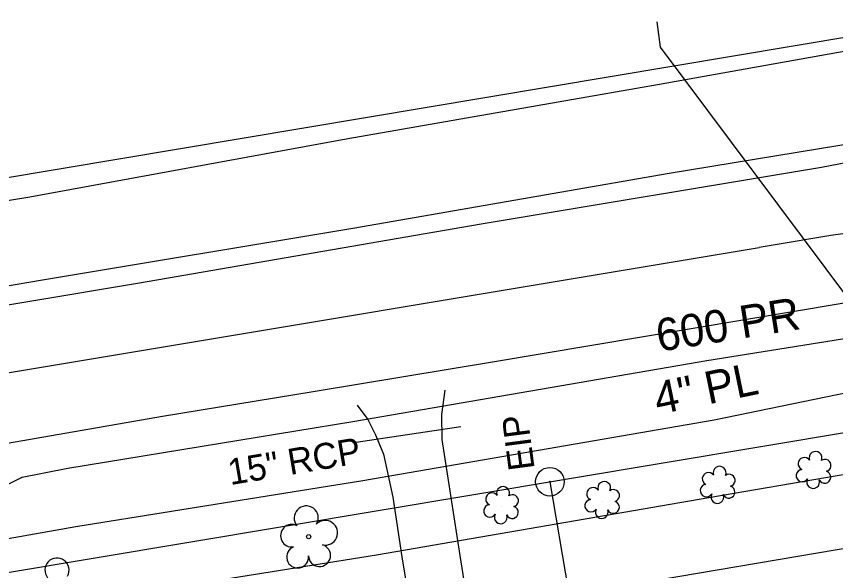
# Model space of a CAD drawing. Extents: x 2364404 to 2371833, y 798876 to 809754.
# Drawn here: x 2368108.5 to 2368234.7, y 807874.9 to 807960.2 of the extents above; entities that cross this region are included whole.
import ezdxf

# ---------------------------------------------------------------- set-up
doc = ezdxf.new("R2010")
doc.units = 0
for name, color, linetype in [('Exist Property Iron Pin CELL', 7, 'Continuous'), ('Exist Property Iron Pin Text', 7, 'Continuous'), ('Exist Property Line', 7, 'Continuous'), ('Exist Right of Way Line', 7, 'Continuous'), ('Exist Roads EOP', 7, 'Continuous'), ('Exist Roads EOP Other', 7, 'Continuous'), ('Exist Structure Minor Pipes RCP 15 Inch', 7, 'Continuous'), ('Exist Structure Minor Pipes RCP 15 Inch Text', 7, 'Continuous'), ('Exist Utilities Gas UG Line SUE LOS B', 7, 'Continuous'), ('Exist Utilities Gas UG Line SUE LOS B Text', 7, 'Continuous'), ('Exist Utilities Other Unknown UG SUE LOS B', 7, 'Continuous'), ('Exist Utilities Sanitary Sewer Manhole Leader', 7, 'Continuous'), ('Exist Utilities Sanitary Sewer UG Line', 7, 'Continuous'), ('Exist Utilities Telephone UG Cable SUE LOS C', 7, 'Continuous'), ('Exist Utilities Telephone UG Cable SUE LOS C Text', 7, 'Continuous'), ('Exist Utilities Water UG Line SUE LOS B', 7, 'Continuous'), ('Exist Vegetation Shrub CELL', 7, 'Continuous'), ('Exist Vegetation Tree CELL', 7, 'Continuous'), ('Prop Horizontal Alignment', 7, 'Continuous')]:
    doc.layers.add(name, color=color, linetype=linetype)

msp = doc.modelspace()

# ---------------------------------------------------------------- linework, layer by layer
at = {"layer": 'Exist Property Iron Pin CELL'}
for radius in [2.2, 0.0707]:
    msp.add_circle((2368190.72, 807888.59), radius, dxfattribs=at)
at = {"layer": 'Exist Property Line'}
msp.add_line((2368190.72, 807888.59), (2368217.51, 807729.25), dxfattribs=at)
at = {"layer": 'Exist Right of Way Line'}
for p, q in [((2367783.4, 807881.3), (2368349.02, 807975.89)), ((2367793.29, 807822.12), (2368269.46, 807901.75))]:
    msp.add_line(p, q, dxfattribs=at)
at = {"layer": 'Exist Roads EOP'}
for points in [[(2368327.15, 807956.52), (2368274.91, 807945.11), (2368232.58, 807936.97), (2368180.11, 807928.25), (2368127.18, 807919.09), (2368078.92, 807911.06), (2368034.07, 807903.44), (2367984.59, 807895.5), (2367945.39, 807888.89), (2367894.54, 807880.53), (2367863.53, 807875.21)], [(2368330.68, 807929.12), (2368282.89, 807923.49), (2368257.36, 807919.77), (2368235.72, 807916.02), (2368181.87, 807907), (2368154.26, 807902.43), (2368131.05, 807898.62), (2368082.95, 807890.29), (2368062.8, 807887.28), (2368038.08, 807883.12), (2367986.91, 807874.75), (2367949.87, 807868.19), (2367928.8, 807864.78), (2367897.29, 807860.14), (2367866.78, 807854.91)]]:
    msp.add_lwpolyline(points, dxfattribs=at)
at = {"layer": 'Exist Roads EOP Other'}
for points in [[(2368177.69, 807872.38), (2368176.91, 807877.23), (2368174.13, 807895.07), (2368174.09, 807898.92), (2368174.61, 807902.68)], [(2368161.02, 807900.36), (2368162.68, 807898.15), (2368163.84, 807895.79), (2368165.08, 807892.84), (2368166.53, 807886.21), (2368167.93, 807877.03), (2368172.78, 807847.56), (2368173.28, 807844.37), (2368175.23, 807832.75), (2368176.39, 807825.31)]]:
    msp.add_lwpolyline(points, dxfattribs=at)
at = {"layer": 'Exist Structure Minor Pipes RCP 15 Inch'}
msp.add_line((2368160.87, 807894.67), (2368176.98, 807897.08), dxfattribs=at)
at = {"layer": 'Exist Utilities Gas UG Line SUE LOS B'}
msp.add_lwpolyline([(2367870.54, 807838.09), (2367919.9, 807848.3), (2367968.48, 807855.53), (2368019.02, 807864.91), (2368064.26, 807872.88), (2368067.9, 807873.62), (2368094.51, 807877.58), (2368117.72, 807881.71), (2368161.92, 807888.8), (2368216.03, 807898.12), (2368260.65, 807907.32), (2368261.62, 807907.37), (2368282.45, 807912.12), (2368324.46, 807917.31), (2368347.86, 807919.04), (2368361.63, 807920.36), (2368385.5, 807921.08), (2368411.16, 807923.46), (2368412.54, 807923.08), (2368413.42, 807922.79)], dxfattribs=at)
at = {"layer": 'Exist Utilities Other Unknown UG SUE LOS B'}
msp.add_lwpolyline([(2367865.57, 807879.8), (2367916.68, 807886.76), (2367964.49, 807894.84), (2368013.92, 807902.8), (2368064.67, 807911.52), (2368112.58, 807919.65), (2368160.35, 807927.6), (2368209.07, 807936.09), (2368258.24, 807944.17), (2368305.66, 807951.87), (2368307.29, 807951.95), (2368330.7, 807955.87), (2368334.34, 807955.66), (2368336.05, 807954.46), (2368339.82, 807934.59), (2368342.66, 807932.92)], dxfattribs=at)
at = {"layer": 'Exist Utilities Sanitary Sewer Manhole Leader'}
msp.add_lwpolyline([(2368262.28, 807882.59), (2368207.76, 807955.48), (2368207.26, 807959.36)], dxfattribs=at)
at = {"layer": 'Exist Utilities Sanitary Sewer UG Line'}
msp.add_line((2368261.35, 807882.59), (2368017.75, 807841.36), dxfattribs=at)
at = {"layer": 'Exist Utilities Telephone UG Cable SUE LOS C'}
msp.add_lwpolyline([(2368104.4, 807876.72), (2368103.94, 807878.32), (2368103.75, 807883), (2368105.99, 807887.59), (2368109.41, 807889.3), (2368116.46, 807890.7), (2368160.35, 807897.88), (2368214.89, 807907.23), (2368259.58, 807914.4), (2368278.5, 807917.6), (2368324.44, 807924.48), (2368339.22, 807921.35), (2368348.06, 807912.11)], dxfattribs=at)
at = {"layer": 'Exist Utilities Water UG Line SUE LOS B'}
for points in [[(2368061.12, 807924.34), (2368110.63, 807932.44), (2368159.36, 807941.39), (2368207.29, 807949.76), (2368255.89, 807958.43), (2368303.66, 807970.11), (2368352.63, 807978.95), (2368406.52, 807986), (2368411.88, 807987.17), (2368430.69, 807989.56), (2368458.99, 807991.26), (2368504.63, 807993.63), (2368554.73, 807997.73), (2368558.03, 807998.11), (2368591.16, 808002.04), (2368605.81, 808004.45), (2368655.67, 808012.45), (2368680.36, 808015.78), (2368688.31, 808016.66)], [(2367871.12, 807828.45), (2367892.35, 807831.6), (2367921.84, 807837.39), (2367970.56, 807845.14), (2367984.76, 807847.38), (2368021.81, 807852.73), (2368062.83, 807858.73), (2368070.48, 807860.37), (2368122.26, 807870.75), (2368136.68, 807872.95), (2368164.02, 807877.33), (2368215.21, 807886.17), (2368262.24, 807894.23), (2368284.02, 807893.82), (2368286.45, 807893.73)]]:
    msp.add_lwpolyline(points, dxfattribs=at)
at = {"layer": 'Exist Vegetation Shrub CELL'}
for p, q in [((2368231.41, 807890.22), (2368231.41, 807890.22)), ((2368216.64, 807887.93), (2368216.64, 807887.93)), ((2368198.85, 807885.59), (2368198.85, 807885.59)), ((2368183.28, 807884.8), (2368183.28, 807884.8))]:
    msp.add_line(p, q, dxfattribs=at)
for centre, radius, start, end in [((2368231.64, 807892.26), 0.99, 334.8391, 200.4717), ((2368229.93, 807891.35), 0.968, 35.8908, 245.4216), ((2368233.08, 807891.09), 0.929, 284.4567, 126.0861), ((2368215.16, 807889.05), 0.968, 35.8908, 245.4216), ((2368216.87, 807889.97), 0.99, 334.8391, 200.4717), ((2368229.61, 807889.52), 0.955, 95.1099, 327.9534), ((2368233.05, 807889.3), 0.937, 204.9913, 73.4601), ((2368199.08, 807887.63), 0.99, 334.8391, 200.4717), ((2368218.32, 807888.8), 0.929, 284.4567, 126.0861), ((2368231.28, 807888.54), 0.984, 151.2797, 21.387), ((2368183.51, 807886.84), 0.99, 334.8391, 200.4717), ((2368197.37, 807886.72), 0.968, 35.8908, 245.4216), ((2368200.52, 807886.46), 0.929, 284.4567, 126.0861), ((2368214.84, 807887.22), 0.955, 95.1099, 327.9534), ((2368218.28, 807887), 0.937, 204.9913, 73.4601), ((2368181.8, 807885.92), 0.968, 35.8908, 245.4216), ((2368184.95, 807885.66), 0.929, 284.4567, 126.0861), ((2368216.52, 807886.24), 0.984, 151.2797, 21.387), ((2368181.48, 807884.09), 0.955, 95.1099, 327.9534), ((2368197.05, 807884.89), 0.955, 95.1099, 327.9534), ((2368200.49, 807884.66), 0.937, 204.9913, 73.4601), ((2368183.15, 807883.11), 0.984, 151.2797, 21.387), ((2368184.92, 807883.87), 0.937, 204.9913, 73.4601), ((2368198.72, 807883.91), 0.984, 151.2797, 21.387)]:
    msp.add_arc(centre, radius, start, end, dxfattribs=at)
at = {"layer": 'Exist Vegetation Tree CELL'}
msp.add_line((2368153.57, 807880.13), (2368153.57, 807880.13), dxfattribs=at)
msp.add_circle((2368153.57, 807880.13), 0.326, dxfattribs=at)
for centre, radius, start, end in [((2368153.18, 807883), 1.86, 330.1651, 219.7134), ((2368156.12, 807880.72), 1.9, 257.1011, 134.1999), ((2368150.96, 807880.28), 1.73, 62.6636, 279.3457), ((2368151.86, 807877.01), 1.69, 111.5671, 6.231), ((2368155.24, 807877.23), 1.7, 181.2822, 74.56), ((2368114.79, 807874.99), 1.86, 330.1651, 219.7134)]:
    msp.add_arc(centre, radius, start, end, dxfattribs=at)
at = {"layer": 'Prop Horizontal Alignment'}
msp.add_line((2367865.16, 807865.06), (2368222.95, 807924.63), dxfattribs=at)
msp.add_arc((2371987.16, 785317.56), 22918.31, 99.30395, 99.453345, dxfattribs=at)

# ---------------------------------------------------------------- texts
at = {"layer": 'Exist Property Iron Pin Text'}
msp.add_text('EIP', height=4, rotation=97.4798, dxfattribs=at).set_placement((2368188.38, 807890.58))
at = {"layer": 'Exist Structure Minor Pipes RCP 15 Inch Text'}
msp.add_text('15" RCP', height=4, rotation=9.5955, dxfattribs=at).set_placement((2368141.49, 807888.06))
at = {"layer": 'Exist Utilities Gas UG Line SUE LOS B Text'}
msp.add_text('4" PL', height=5, rotation=11.6447, dxfattribs=at).set_placement((2368207.34, 807898.89))
at = {"layer": 'Exist Utilities Telephone UG Cable SUE LOS C Text'}
msp.add_text('600 PR', height=5, rotation=9.1084, dxfattribs=at).set_placement((2368207.51, 807908.58))

doc.saveas('drawing.dxf')
